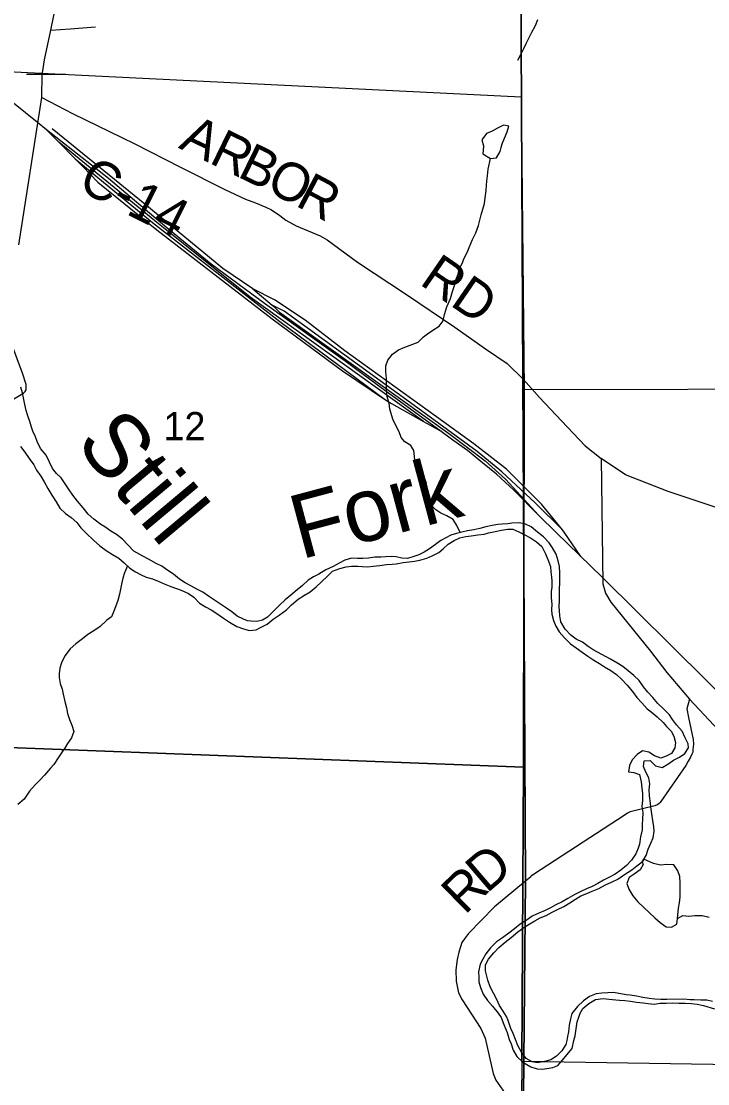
# Model space of a CAD drawing. Extents: x 0 to 34, y 0 to 22.
# Drawn here: x 5.549 to 6.566, y 14.969 to 16.545 of the extents above; entities that cross this region are included whole.
import ezdxf

# ---------------------------------------------------------------- set-up
doc = ezdxf.new("R2010")
doc.units = 0
doc.layers.add('Default', color=7, linetype='Continuous')

msp = doc.modelspace()

# ---------------------------------------------------------------- linework, layer by layer
at = {"layer": 'Default'}
for p, q in [((5.5861, 16.3845), (5.6042, 16.3661)), ((5.6042, 16.3661), (5.6285, 16.3411)), ((5.8916, 16.1485), (5.9207, 16.124)), ((5.9315, 16.114), (5.9458, 16.1003)), ((6.1447, 15.9518), (6.169, 15.9383)), ((6.3414, 15.7868), (6.316, 15.8124))]:
    msp.add_line(p, q, dxfattribs=at)
for points in [[(6.2892, 14.1), (8.9, 14.1), (8.9, 17.02), (8.2009, 17.0196), (7.211, 17.0191), (7.2045, 17.0191), (6.9328, 17.0189), (6.927, 17.0189), (6.6903, 17.0144), (6.3876, 17.0173), (6.3215, 17.0189), (6.2871, 17.0188), (6.2922, 16.0152), (6.2959, 15.2705), (6.2926, 14.8972), (6.2889, 14.4906), (6.2892, 14.18)], [(5.2975, 16.482), (6.2896, 16.4334), (6.2943, 15.9991), (6.2933, 15.4392), (5.284, 15.4777)], [(6.2943, 15.9991), (7.265, 16.0012), (7.2656, 14.9873), (6.2908, 15.0024), (6.2933, 15.4392)], [(5.284, 15.4777), (6.2933, 15.4392), (6.2908, 15.0024), (6.2858, 14.4391), (5.2822, 14.472)], [(6.2854, 14.1), (7.2754, 14.1), (7.2656, 14.9873), (6.2908, 15.0024), (6.2858, 14.4391)]]:
    msp.add_lwpolyline(points, close=True, dxfattribs=at)
for points in [[(2.1, 17.0156), (2.1, 14.1), (6.2892, 14.1), (6.2892, 14.18), (6.2889, 14.4906), (6.2926, 14.8972), (6.2959, 15.2705), (6.2922, 16.0152), (6.2871, 17.0188)], [(5.5804, 16.4716), (5.5828, 16.4882), (5.5923, 16.5322), (5.5965, 16.5516), (5.6013, 16.5736), (5.6015, 16.575), (5.609, 16.6187), (5.612, 16.6357), (5.6252, 16.7002), (5.6361, 16.7532), (5.6497, 16.819), (5.6611, 16.8747), (5.6615, 16.8796), (5.6612, 16.8833), (5.661, 16.884), (5.6598, 16.8881), (5.6575, 16.8937), (5.6209, 16.9478), (5.5789, 17.012)], [(5.5861, 16.3845), (5.5724, 16.3953), (5.5193, 16.4381), (5.4802, 16.4691), (5.4669, 16.4789), (5.4374, 16.4998), (5.4065, 16.5213), (5.3742, 16.5456), (5.3315, 16.5782), (5.283, 16.6114), (5.2424, 16.6404), (5.2378, 16.6435)], [(6.3139, 16.5475), (6.3102, 16.5383), (6.3051, 16.5287), (6.3006, 16.5199), (6.2966, 16.5119), (6.2933, 16.5043), (6.2885, 16.4955), (6.2844, 16.4871)], [(5.5923, 16.5322), (5.6208, 16.5343), (5.6588, 16.5372)], [(5.579, 16.4321), (5.5797, 16.4666), (5.5804, 16.4716)], [(5.5564, 16.4666), (5.5797, 16.4666), (5.6146, 16.4668)], [(5.5447, 16.2139), (5.579, 16.4321)], [(5.579, 16.4321), (5.6245, 16.4085), (5.7171, 16.3633), (5.7844, 16.329), (5.8505, 16.296), (5.8812, 16.2813), (5.8957, 16.2762), (5.911, 16.2696), (5.9197, 16.2655), (5.9319, 16.2572), (5.9408, 16.2505), (5.9559, 16.2421), (5.974, 16.2344), (5.9916, 16.2269), (6.002, 16.2209), (6.0471, 16.1878), (6.1195, 16.1402), (6.1913, 16.0916), (6.2366, 16.0596), (6.2691, 16.0375), (6.2924, 16.0147), (6.3096, 15.9955)], [(6.2663, 16.3906), (6.2634, 16.3911), (6.2547, 16.3868), (6.2464, 16.3825), (6.2381, 16.379), (6.2314, 16.3694), (6.2338, 16.3603), (6.2335, 16.3542), (6.2329, 16.3485), (6.2444, 16.3418)], [(6.2444, 16.3418), (6.2531, 16.3427), (6.2586, 16.3519), (6.2601, 16.358), (6.2615, 16.3637), (6.2648, 16.3717), (6.2689, 16.3813), (6.2714, 16.3897), (6.2663, 16.3906)], [(5.9458, 16.1003), (5.9091, 16.1265), (5.8301, 16.1852), (5.7641, 16.239), (5.6779, 16.3119), (5.5861, 16.3845)], [(5.8916, 16.1485), (5.8473, 16.1787), (5.7318, 16.2741), (5.5944, 16.3856)], [(6.1447, 15.9518), (5.888, 16.136), (5.7466, 16.2491), (5.6042, 16.3661)], [(5.6285, 16.3411), (5.6398, 16.3297), (5.6618, 16.3067), (5.7493, 16.236), (5.9206, 16.1041), (6.0248, 16.0268), (6.0884, 15.984)], [(5.6285, 16.3411), (5.743, 16.2468), (5.9321, 16.0998), (6.0884, 15.984)], [(6.1994, 15.787), (6.1945, 15.7974), (6.1887, 15.8061), (6.1795, 15.8116), (6.1707, 15.8157), (6.1631, 15.8205), (6.1558, 15.828), (6.1511, 15.8359), (6.1479, 15.8435), (6.147, 15.8518), (6.1492, 15.8602), (6.1461, 15.8681), (6.1391, 15.8745), (6.1348, 15.8828), (6.132, 15.8941), (6.1315, 15.8998), (6.1303, 15.9085), (6.126, 15.9161), (6.1172, 15.9216), (6.1118, 15.928), (6.1086, 15.9363), (6.1035, 15.9465), (6.0992, 15.9552), (6.0968, 15.9635), (6.0948, 15.9699), (6.0939, 15.979), (6.0911, 15.9881), (6.0899, 15.9983), (6.0901, 16.0074), (6.09, 16.0154), (6.0891, 16.0253), (6.089, 16.0344), (6.0919, 16.0424), (6.099, 16.0516), (6.108, 16.0578), (6.1174, 16.0621), (6.1371, 16.0692), (6.1449, 16.0773), (6.1509, 16.0816), (6.1588, 16.087), (6.1682, 16.0932), (6.1742, 16.1009), (6.176, 16.1104), (6.1792, 16.1218), (6.1847, 16.1341), (6.188, 16.1447), (6.1913, 16.1547), (6.1934, 16.1627), (6.196, 16.1703), (6.1978, 16.1779), (6.2029, 16.1871), (6.2048, 16.1928), (6.2096, 16.2024), (6.2125, 16.2096), (6.2173, 16.2215), (6.2224, 16.2314), (6.2264, 16.2425), (6.2282, 16.2505), (6.2304, 16.2581), (6.2329, 16.2665), (6.2351, 16.2749), (6.2365, 16.2833), (6.2375, 16.2943), (6.2381, 16.3023), (6.2388, 16.308), (6.2398, 16.316), (6.2408, 16.3258), (6.2444, 16.3418)], [(6.3509, 15.7908), (6.3198, 15.8292), (6.2678, 15.8808), (6.2195, 15.9187), (6.1639, 15.9588), (6.0281, 16.0564), (5.9692, 16.1021), (5.9239, 16.1321), (5.8916, 16.1485)], [(6.3509, 15.7908), (6.3102, 15.8312), (6.2609, 15.8769), (6.2244, 15.9071), (6.1366, 15.9713), (5.9383, 16.1153), (5.9207, 16.124)], [(5.9207, 16.124), (5.9229, 16.1222), (5.9315, 16.114)], [(5.9315, 16.114), (6.184, 15.9328), (6.2362, 15.8933), (6.2662, 15.866), (6.316, 15.8124)], [(6.169, 15.9383), (6.0897, 15.996), (6.0288, 16.041), (5.9458, 16.1003)], [(5.5373, 15.9852), (5.5516, 15.9938), (5.5542, 15.9963), (5.5556, 15.9988), (5.5559, 16.0036), (5.5557, 16.0064), (5.5506, 16.0234), (5.5345, 16.0659)], [(5.8837, 15.6559), (5.8779, 15.6585), (5.8688, 15.6629), (5.8607, 15.6693), (5.8526, 15.6749), (5.8262, 15.6927), (5.8177, 15.6987), (5.8086, 15.7031), (5.8001, 15.7079), (5.7913, 15.7123), (5.7833, 15.7179), (5.7741, 15.7254), (5.7656, 15.7306), (5.7568, 15.7369), (5.7484, 15.741), (5.7373, 15.7473), (5.7289, 15.7517), (5.7155, 15.7595), (5.7066, 15.7689), (5.6985, 15.7771), (5.6897, 15.7842), (5.6812, 15.789), (5.6724, 15.7953), (5.6663, 15.799), (5.6563, 15.8069), (5.6478, 15.814), (5.6401, 15.8237), (5.632, 15.8335), (5.625, 15.8425), (5.6196, 15.8504), (5.6134, 15.859), (5.6076, 15.8681), (5.6006, 15.8744), (5.5948, 15.8819), (5.5905, 15.8914), (5.5854, 15.9015), (5.5769, 15.9117), (5.5722, 15.9219), (5.5695, 15.9287), (5.5659, 15.9373), (5.5635, 15.9434), (5.5611, 15.9517), (5.5584, 15.96), (5.556, 15.9679), (5.5536, 15.977), (5.5503, 15.9944), (5.5479, 16.0028)], [(6.3096, 15.9955), (6.3168, 15.9874), (6.3494, 15.9526), (6.3845, 15.9154), (6.4082, 15.8968), (6.4109, 15.7111), (6.4148, 15.6972), (6.4226, 15.6839), (6.4812, 15.6108), (6.5058, 15.5794), (6.5394, 15.5399), (6.5899, 15.4855)], [(6.0884, 15.984), (6.0972, 15.9782), (6.1447, 15.9518)], [(6.316, 15.8124), (6.2786, 15.85), (6.2532, 15.8736), (6.2324, 15.8906), (6.2101, 15.9086), (6.1885, 15.9242), (6.169, 15.9383)], [(5.5476, 15.9147), (5.5538, 15.906), (5.5601, 15.8966), (5.5674, 15.8872), (5.5709, 15.8797), (5.5775, 15.8707), (5.5826, 15.8624), (5.588, 15.8522), (5.5939, 15.8424), (5.6005, 15.8327), (5.6056, 15.8232), (5.614, 15.815), (5.6225, 15.8094), (5.6309, 15.802), (5.6367, 15.7941), (5.6452, 15.7854), (5.6556, 15.7757), (5.6648, 15.7671), (5.6744, 15.7604), (5.684, 15.7545), (5.6932, 15.7489), (5.7013, 15.7418), (5.7094, 15.7343), (5.7178, 15.7288), (5.7262, 15.7243), (5.7339, 15.721), (5.743, 15.7181), (5.7514, 15.7148), (5.7606, 15.7111), (5.7705, 15.7071), (5.7858, 15.7013), (5.7965, 15.6965), (5.8046, 15.6909), (5.8127, 15.6823), (5.8215, 15.6767), (5.8299, 15.6723), (5.8387, 15.6671), (5.8483, 15.66), (5.8571, 15.654)], [(6.8988, 15.7495), (6.8938, 15.7425), (6.889, 15.738), (6.8826, 15.7351), (6.8742, 15.7325), (6.8615, 15.7302), (6.8472, 15.7284), (6.8382, 15.7287), (6.832, 15.7294), (6.8206, 15.7316), (6.8131, 15.7338), (6.7712, 15.7494), (6.6588, 15.7973), (6.616, 15.8117), (6.5078, 15.8479), (6.4443, 15.8724), (6.4082, 15.8968)], [(5.8571, 15.654), (5.8679, 15.6477), (5.8778, 15.6441), (5.8869, 15.6416), (5.8968, 15.6425), (5.9043, 15.6464), (5.913, 15.651), (5.922, 15.6584), (5.9307, 15.6642), (5.9415, 15.6723), (5.949, 15.6796), (5.9588, 15.6881), (5.9682, 15.694), (5.9769, 15.699), (5.9855, 15.7064), (6.002, 15.7218), (6.0098, 15.7295), (6.0208, 15.7338), (6.0302, 15.7362), (6.0382, 15.7371), (6.0477, 15.7369), (6.0538, 15.7366), (6.0618, 15.7363), (6.0701, 15.7372), (6.08, 15.7381), (6.0902, 15.7397), (6.0985, 15.7402), (6.1042, 15.7407), (6.1148, 15.7424), (6.1236, 15.7433), (6.1315, 15.7445), (6.1395, 15.7458), (6.1497, 15.7489), (6.1587, 15.7529), (6.1678, 15.7576), (6.1742, 15.7626), (6.1813, 15.7699), (6.1903, 15.775), (6.1986, 15.7793), (6.2077, 15.7809), (6.2157, 15.7822), (6.2255, 15.7834), (6.235, 15.7847), (6.2414, 15.7863), (6.2513, 15.7887), (6.2607, 15.7904), (6.2694, 15.792), (6.2774, 15.7918), (6.2862, 15.7881), (6.2942, 15.784), (6.3034, 15.7792), (6.3126, 15.7733), (6.3203, 15.7662), (6.3258, 15.7556), (6.329, 15.7469), (6.3329, 15.7364), (6.3338, 15.7288), (6.3347, 15.7208), (6.3351, 15.7151), (6.3349, 15.7056), (6.3342, 15.6999), (6.3343, 15.69), (6.3349, 15.6809), (6.3346, 15.6722), (6.3351, 15.6661), (6.3375, 15.6567), (6.341, 15.648), (6.3461, 15.6397), (6.3538, 15.6307), (6.363, 15.6221), (6.3711, 15.6158), (6.3803, 15.6094), (6.3884, 15.6035), (6.3972, 15.5979), (6.4056, 15.5927), (6.4133, 15.5879), (6.4225, 15.5823), (6.4309, 15.5764), (6.4386, 15.5696), (6.4467, 15.5606), (6.4545, 15.5513), (6.461, 15.5422), (6.4684, 15.5344), (6.4765, 15.5257), (6.4822, 15.5209), (6.4911, 15.5138), (6.4999, 15.5052), (6.505, 15.4992), (6.5119, 15.4925), (6.5158, 15.4849), (6.5186, 15.4758), (6.5176, 15.4675), (6.5124, 15.4594), (6.5045, 15.4555), (6.4965, 15.4524), (6.4874, 15.4557), (6.4789, 15.4612), (6.4694, 15.4634), (6.4615, 15.4576), (6.4544, 15.4499), (6.4504, 15.4415)], [(6.4709, 15.4402), (6.4719, 15.4486), (6.481, 15.4487), (6.4887, 15.4409), (6.4986, 15.4387), (6.5073, 15.4434), (6.5156, 15.4492), (6.5246, 15.4539), (6.5325, 15.4593), (6.5377, 15.4678), (6.5372, 15.4734), (6.5329, 15.4825), (6.5282, 15.4923), (6.5201, 15.5017), (6.5139, 15.5099), (6.5093, 15.5167), (6.5012, 15.525), (6.4923, 15.5336), (6.485, 15.5422), (6.4773, 15.5501), (6.4711, 15.5583), (6.4645, 15.5677), (6.4568, 15.5748), (6.4483, 15.5819), (6.4403, 15.5883), (6.4314, 15.5935), (6.4219, 15.599), (6.4027, 15.6094), (6.3966, 15.6131), (6.3889, 15.6179), (6.3805, 15.6243), (6.3713, 15.6287), (6.3632, 15.6346), (6.3548, 15.6436), (6.3485, 15.6546), (6.3469, 15.6633), (6.3464, 15.6712), (6.3459, 15.6769), (6.3465, 15.6864), (6.3464, 15.6955), (6.3467, 15.7031), (6.3469, 15.7126), (6.3468, 15.7187), (6.3471, 15.7274), (6.3466, 15.7365), (6.3446, 15.7449), (6.3414, 15.7547), (6.3363, 15.7641), (6.3313, 15.7716), (6.3228, 15.7806), (6.3136, 15.7873), (6.3043, 15.7952), (6.2963, 15.7996), (6.2868, 15.8014), (6.2758, 15.8009), (6.2701, 15.8), (6.2614, 15.7995), (6.2549, 15.799), (6.2466, 15.7974), (6.2371, 15.7954), (6.2284, 15.793), (6.2193, 15.7909), (6.2099, 15.7893), (6.2019, 15.7877), (6.1936, 15.7856), (6.1856, 15.7829), (6.1706, 15.7751), (6.1627, 15.7693), (6.1537, 15.763), (6.1458, 15.758), (6.1378, 15.7541), (6.1303, 15.7513), (6.1212, 15.7485), (6.1128, 15.7488), (6.1045, 15.751), (6.098, 15.7516), (6.0885, 15.7511), (6.0817, 15.7506), (6.0729, 15.7505), (6.0635, 15.7489), (6.0551, 15.7484), (6.0472, 15.7486), (6.038, 15.7489), (6.0282, 15.7461), (6.0199, 15.7414), (6.0109, 15.7367), (5.9999, 15.7316), (5.9898, 15.725), (5.9819, 15.7211), (5.974, 15.7161), (5.9653, 15.7084), (5.9574, 15.7022), (5.9484, 15.6941), (5.9398, 15.6871), (5.9312, 15.6794), (5.9215, 15.6694), (5.9136, 15.6617), (5.9061, 15.657), (5.8977, 15.655), (5.8894, 15.6553), (5.8837, 15.6559)], [(6.378, 15.7513), (6.3536, 15.7875), (6.3509, 15.7908)], [(6.6156, 15.5167), (6.41, 15.7203), (6.3414, 15.7868)], [(5.7058, 15.7376), (5.7015, 15.7274), (5.6993, 15.7194), (5.6972, 15.7106), (5.6958, 15.703), (5.694, 15.6958), (5.6918, 15.6862), (5.6882, 15.6767), (5.686, 15.6702), (5.6823, 15.6618), (5.6756, 15.6572), (5.6654, 15.6475), (5.656, 15.6413), (5.6474, 15.6355), (5.6395, 15.6293), (5.6294, 15.6219), (5.6211, 15.6146), (5.6129, 15.6039), (5.6081, 15.5939), (5.6056, 15.5859), (5.6046, 15.5776), (5.6046, 15.5719), (5.6063, 15.5631), (5.6091, 15.5545), (5.6107, 15.5473), (5.6131, 15.5363), (5.6155, 15.5268), (5.6172, 15.5185), (5.62, 15.5098), (5.6235, 15.5011), (5.6267, 15.4917), (5.623, 15.4825), (5.6171, 15.4741), (5.6137, 15.4683), (5.6093, 15.4618), (5.6033, 15.4526), (5.5966, 15.443), (5.5918, 15.4373), (5.5828, 15.4273), (5.5761, 15.4199), (5.569, 15.4126), (5.5608, 15.4034), (5.5526, 15.3915), (5.5432, 15.3838)], [(6.5394, 15.5399), (6.5351, 15.5255), (6.5378, 15.5127), (6.5444, 15.4802), (6.5449, 15.473), (6.5443, 15.4653), (6.5439, 15.4613), (6.5424, 15.4581), (6.5406, 15.4539), (6.5372, 15.4478), (6.5336, 15.4413), (6.4968, 15.388), (6.4957, 15.3867), (6.4941, 15.3851), (6.492, 15.3837), (6.4906, 15.3828), (6.4889, 15.382), (6.488, 15.3818), (6.4513, 15.3725), (6.4475, 15.3709), (6.4423, 15.3675), (6.3092, 15.2809), (6.3047, 15.2771), (6.3039, 15.2765)], [(6.4504, 15.4415), (6.4486, 15.4323), (6.4566, 15.4313), (6.465, 15.428), (6.4674, 15.417), (6.4687, 15.4079), (6.4696, 15.3992), (6.4697, 15.3893), (6.4687, 15.3806), (6.47, 15.3715), (6.4697, 15.3616), (6.4691, 15.3544), (6.4688, 15.346), (6.4667, 15.3357), (6.465, 15.3247), (6.4631, 15.319), (6.4598, 15.3106), (6.4531, 15.301), (6.4457, 15.2929), (6.4374, 15.2863), (6.4288, 15.2805), (6.4197, 15.2751), (6.4118, 15.2712), (6.4035, 15.2665), (6.3949, 15.2618), (6.3865, 15.2583), (6.3783, 15.2544), (6.3692, 15.25), (6.359, 15.2442), (6.3504, 15.2391), (6.3409, 15.2348), (6.333, 15.2305), (6.3251, 15.2266), (6.3157, 15.2223), (6.3059, 15.218), (6.2972, 15.2114), (6.2882, 15.206), (6.2799, 15.199), (6.2713, 15.1928), (6.2619, 15.1859), (6.2533, 15.1797), (6.2443, 15.1712), (6.2372, 15.162), (6.2327, 15.1543), (6.2287, 15.1467), (6.2266, 15.1352), (6.2267, 15.1276), (6.2271, 15.1208), (6.2292, 15.1121), (6.2335, 15.1023), (6.2397, 15.0929), (6.247, 15.0843), (6.2555, 15.0741), (6.2598, 15.0677), (6.2641, 15.0575), (6.2689, 15.0454), (6.2717, 15.0352), (6.2748, 15.0288), (6.278, 15.0194), (6.2834, 15.01), (6.2923, 15.0013), (6.3042, 14.9947), (6.3133, 14.9914), (6.3213, 14.9911), (6.3304, 14.9924), (6.3365, 14.9936), (6.344, 14.9964), (6.3507, 15.0044), (6.3575, 15.0121), (6.3653, 15.0217), (6.3678, 15.0336), (6.3696, 15.0404), (6.3713, 15.0511), (6.3727, 15.0613), (6.3749, 15.0682), (6.3771, 15.0739), (6.3811, 15.0808), (6.3901, 15.0886), (6.3996, 15.0944), (6.4113, 15.0961), (6.4201, 15.0951), (6.4299, 15.0941), (6.4356, 15.0934), (6.4433, 15.0927), (6.4516, 15.0921), (6.4608, 15.0903), (6.4703, 15.0893), (6.4779, 15.0883), (6.487, 15.0877), (6.4957, 15.0889), (6.5044, 15.089), (6.5136, 15.0895), (6.5234, 15.0889), (6.5329, 15.0887), (6.542, 15.0884), (6.5504, 15.0874), (6.5599, 15.0856), (6.576, 15.0806)], [(6.5735, 15.0912), (6.5651, 15.0933), (6.556, 15.0936), (6.5461, 15.0938), (6.5404, 15.0941), (6.5306, 15.0947), (6.5055, 15.0944), (6.4968, 15.0946), (6.4876, 15.0949), (6.4793, 15.0959), (6.4698, 15.0973), (6.4606, 15.0991), (6.4511, 15.1008), (6.4454, 15.1011), (6.4264, 15.1046), (6.418, 15.1045), (6.4093, 15.1036), (6.401, 15.1028), (6.3908, 15.0988), (6.3821, 15.0926), (6.3731, 15.0838), (6.3649, 15.0738), (6.3628, 15.0658), (6.361, 15.0562), (6.3596, 15.0463), (6.3582, 15.0395), (6.3571, 15.0334), (6.3557, 15.0277), (6.3501, 15.0181), (6.3419, 15.0104), (6.3336, 15.005), (6.3242, 15.0022), (6.3139, 15.0005), (6.306, 15.0019), (6.2971, 15.0071), (6.2902, 15.0165), (6.2847, 15.0263), (6.2812, 15.035), (6.278, 15.0441), (6.2745, 15.0516), (6.2705, 15.0633), (6.2681, 15.0694), (6.2627, 15.0773), (6.2577, 15.0855), (6.2537, 15.0942), (6.2487, 15.104), (6.2436, 15.1134), (6.2404, 15.1233), (6.238, 15.1308), (6.2368, 15.1369), (6.2367, 15.146), (6.2411, 15.1544), (6.2489, 15.1637), (6.2564, 15.1714), (6.2658, 15.1795), (6.2748, 15.1864), (6.2849, 15.1949), (6.2936, 15.2011), (6.3015, 15.2062), (6.3101, 15.2109), (6.3177, 15.2155), (6.3267, 15.2191), (6.3358, 15.2238), (6.3437, 15.2277), (6.3527, 15.2323), (6.3618, 15.2378), (6.3701, 15.2432), (6.3783, 15.2483), (6.387, 15.2514), (6.395, 15.255), (6.4048, 15.2589), (6.4146, 15.2644), (6.4244, 15.2687), (6.433, 15.273), (6.4428, 15.28), (6.4537, 15.2866), (6.4612, 15.2924), (6.4691, 15.2986), (6.4747, 15.3081), (6.478, 15.3173), (6.482, 15.3261), (6.4853, 15.3341), (6.4867, 15.344), (6.4862, 15.3504), (6.4846, 15.3599), (6.4833, 15.3698), (6.482, 15.38), (6.4815, 15.3857), (6.4799, 15.3963), (6.4794, 15.4054), (6.4804, 15.4145), (6.4791, 15.4233), (6.4744, 15.4315), (6.4709, 15.4402)], [(6.5216, 15.2146), (6.5229, 15.2298), (6.5243, 15.2378), (6.5253, 15.2466), (6.5252, 15.2553), (6.5255, 15.2614), (6.5254, 15.2675), (6.5249, 15.2769), (6.5221, 15.2853), (6.5159, 15.2939), (6.5056, 15.2945), (6.4962, 15.2936), (6.4859, 15.2961), (6.4713, 15.3023), (6.4691, 15.2986)], [(6.4691, 15.2986), (6.4703, 15.2948), (6.4659, 15.2867), (6.4572, 15.2802), (6.4497, 15.2751), (6.4461, 15.2663), (6.4492, 15.258), (6.455, 15.2482), (6.4628, 15.2392), (6.4797, 15.2228), (6.4878, 15.2153), (6.4955, 15.2085), (6.5047, 15.2022), (6.5127, 15.2016), (6.5206, 15.2062), (6.5216, 15.2146)], [(6.4691, 15.2986), (6.4703, 15.2948), (6.4659, 15.2867), (6.4572, 15.2802), (6.4497, 15.2751), (6.4461, 15.2663), (6.4492, 15.258), (6.455, 15.2482), (6.4628, 15.2392), (6.4797, 15.2228), (6.4878, 15.2153), (6.4955, 15.2085), (6.5047, 15.2022), (6.5127, 15.2016), (6.5206, 15.2062), (6.5216, 15.2146), (6.5291, 15.2189), (6.5383, 15.2179), (6.547, 15.2188), (6.558, 15.2189), (6.5683, 15.2164)], [(6.3039, 15.2765), (6.2961, 15.27), (6.2499, 15.2316), (6.2115, 15.1924), (6.2056, 15.1844), (6.2019, 15.1787), (6.1996, 15.1727), (6.197, 15.1645), (6.1947, 15.1539), (6.1927, 15.1385), (6.1932, 15.1215), (6.1965, 15.1043), (6.2023, 15.0937), (6.2298, 15.0514), (6.2361, 15.037), (6.2481, 14.9846), (6.2523, 14.9748), (6.2692, 14.9501), (6.2708, 14.9477)]]:
    msp.add_lwpolyline(points, dxfattribs=at)

# ---------------------------------------------------------------- texts
for s, height, rotation, p in [('A', 0.0568, 334.0801, (5.7804, 16.3578)), ('R', 0.0568, 334.079, (5.8253, 16.3359)), ('B', 0.0568, 333.9411, (5.8673, 16.3156)), ('C-14', 0.05682, 333.4338, (5.6306, 16.2961)), ('O', 0.0568, 332.9951, (5.909, 16.2952)), ('R', 0.0568, 332.1222, (5.9533, 16.2726)), ('RD', 0.05682, 325.4924, (6.1374, 16.1561)), ('Still', 0.09472, 309.9676, (5.627, 15.9187)), ('12', 0.04186, 0, (5.7593, 15.9239)), ('Fork', 0.09471, 14.9667, (5.9628, 15.7468)), ('D', 0.0568, 40.5393, (6.2385, 15.2508)), ('R', 0.0568, 44.3873, (6.2059, 15.2188))]:
    msp.add_text(s, height=height, rotation=rotation, dxfattribs=at).set_placement(p)

doc.saveas('drawing.dxf')
